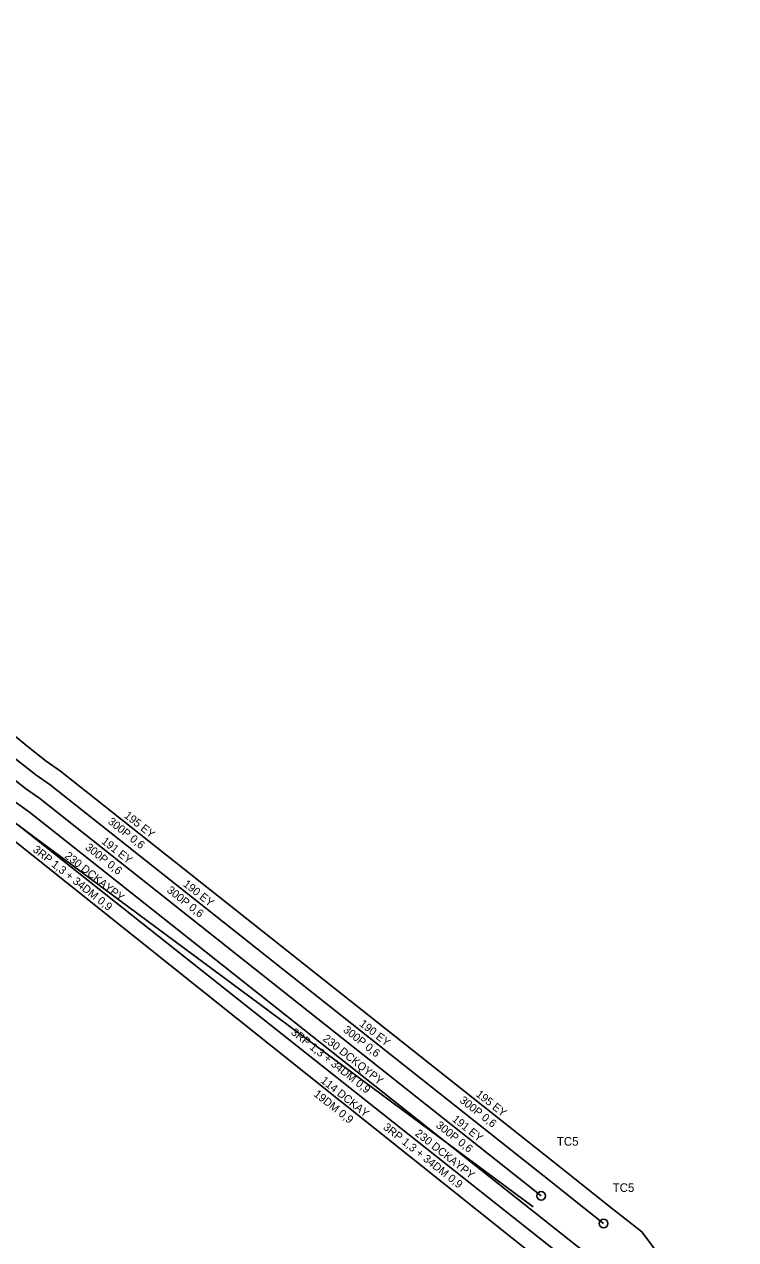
# Model space of a CAD drawing. Extents: x -756413 to -755757, y -1139003 to -1138237.
# Drawn here: x -756098.8 to -756067.7, y -1138473.1 to -1138419.9 of the extents above; entities that cross this region are included whole.
import ezdxf

# ---------------------------------------------------------------- set-up
doc = ezdxf.new("R2010")
doc.units = 0
for name, color, linetype in [('f006_osa_trasy', 7, 'Continuous'), ('f307_kabel_metal', 7, 'Continuous'), ('f307_kabel_metal_ann', 7, 'Continuous'), ('f307_spojka_metal', 7, 'Continuous'), ('f307_spojka_metal_ann', 7, 'Continuous')]:
    doc.layers.add(name, color=color, linetype=linetype)

msp = doc.modelspace()

# ---------------------------------------------------------------- linework, layer by layer
at = {"layer": 'f006_osa_trasy'}
msp.add_lwpolyline([(-756195.84, -1138343.55), (-756185.35, -1138358.4), (-756177.88, -1138364.69), (-756170.53, -1138375.55), (-756161.61, -1138387.83), (-756142.93, -1138413.51), (-756121.74, -1138435.57), (-756109.6, -1138449.6), (-756100.9, -1138454.08), (-756099.19, -1138454.87), (-756076.56, -1138471.66)], dxfattribs=at)
at = {"layer": 'f307_kabel_metal'}
for points in [[(-756159.245, -1138384.875), (-756133.581, -1138414.937), (-756133.096, -1138415.504), (-756116.833, -1138434.471), (-756116.406, -1138434.968), (-756116.374, -1138435.005), (-756112.089, -1138439.831), (-756112.46, -1138440.144), (-756098.699, -1138451.492), (-756097.846, -1138452.155), (-756097.226, -1138452.599), (-756075.319, -1138469.96), (-756074.731, -1138470.426), (-756073.006, -1138471.794), (-756072.418, -1138472.26), (-756071.808, -1138472.743), (-756069.341, -1138476.062)], [(-756159.832, -1138385.342), (-756134.151, -1138415.425), (-756133.665, -1138415.992), (-756117.402, -1138434.959), (-756116.972, -1138435.46), (-756116.936, -1138435.501), (-756113.16, -1138439.754), (-756113.63, -1138440.151), (-756099.168, -1138452.077), (-756098.295, -1138452.756), (-756097.678, -1138453.198), (-756075.785, -1138470.548), (-756075.197, -1138471.014), (-756073.472, -1138472.382)], [(-756160.419, -1138385.809), (-756134.721, -1138415.912), (-756134.235, -1138416.48), (-756117.971, -1138435.447), (-756117.539, -1138435.95), (-756117.499, -1138435.996), (-756114.231, -1138439.677), (-756114.803, -1138440.16), (-756114.786, -1138440.18), (-756114.258, -1138440.606), (-756099.637, -1138452.663), (-756098.744, -1138453.357), (-756098.13, -1138453.797), (-756076.201, -1138471.176)], [(-756118.06, -1138436.494), (-756115.302, -1138439.6), (-756115.868, -1138440.078), (-756115.309, -1138440.722), (-756114.732, -1138441.187), (-756100.106, -1138453.248), (-756099.193, -1138453.958), (-756098.582, -1138454.396), (-756073.437, -1138474.323), (-756067.467, -1138482.356), (-756067.103, -1138482.845), (-756053.982, -1138492.668), (-756043.489, -1138502.85), (-756028.271, -1138519.778)], [(-756115.87, -1138441.22), (-756100.575, -1138453.833), (-756099.642, -1138454.559), (-756099.033, -1138454.995), (-756073.98, -1138474.85), (-756068.069, -1138482.803), (-756067.64, -1138483.38), (-756054.47, -1138493.24), (-756044.03, -1138503.37), (-756028.82, -1138520.29), (-756023.791, -1138525.491), (-756023.27, -1138526.03), (-756020.86, -1138528.62), (-756019.97, -1138529.61), (-756019.66, -1138535.02), (-756014.34, -1138539.73), (-756002.7, -1138549.54), (-756020.63, -1138568.61), (-756010.79, -1138582.3), (-756003.44, -1138591.94)], [(-756109.723, -1138449.702), (-756101.395, -1138453.937), (-756074.523, -1138475.377), (-756068.671, -1138483.25), (-756068.177, -1138483.915), (-756054.958, -1138493.812), (-756044.571, -1138503.89), (-756040.521, -1138508.396)]]:
    msp.add_lwpolyline(points, dxfattribs=at)
at = {"layer": 'f307_spojka_metal'}
for centre in [(-756076.201, -1138471.176), (-756073.472, -1138472.382)]:
    msp.add_circle(centre, 0.188, dxfattribs=at)

# ---------------------------------------------------------------- texts
at = {"layer": 'f307_kabel_metal_ann'}
for s, p in [(' 300P 0,6', (-756095.278, -1138454.781)), ('195 EY', (-756094.465, -1138454.595)), ('191 EY', (-756095.457, -1138455.723)), (' 3RP 1,3 + 34DM 0,9', (-756098.563, -1138456.006)), ('230 DCKAYPY', (-756097.069, -1138456.36)), (' 300P 0,6', (-756096.27, -1138455.909)), (' 300P 0,6', (-756092.701, -1138457.78)), ('190 EY', (-756091.888, -1138457.594)), ('190 EY', (-756084.178, -1138463.704)), (' 3RP 1,3 + 34DM 0,9', (-756087.274, -1138463.996)), ('230 DCKQYPY', (-756085.78, -1138464.35)), (' 300P 0,6', (-756084.991, -1138463.89)), ('114 DCKAY', (-756085.874, -1138466.189)), (' 19DM 0,9', (-756086.279, -1138466.698)), (' 300P 0,6', (-756079.899, -1138466.969)), ('195 EY', (-756079.086, -1138466.783)), (' 300P 0,6', (-756080.935, -1138468.063)), ('191 EY', (-756080.122, -1138467.877)), (' 3RP 1,3 + 34DM 0,9', (-756083.243, -1138468.147)), ('230 DCKAYPY', (-756081.749, -1138468.501))]:
    msp.add_text(s, height=0.35, rotation=321.6, dxfattribs=at).set_placement(p)
at = {"layer": 'f307_spojka_metal_ann'}
for p in [(-756075.517, -1138468.979), (-756073.077, -1138471.001)]:
    msp.add_text('TC5', height=0.375, dxfattribs=at).set_placement(p)

doc.saveas('drawing.dxf')
